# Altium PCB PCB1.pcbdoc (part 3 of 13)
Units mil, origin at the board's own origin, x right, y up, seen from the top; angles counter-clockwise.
Board outline 5895.51 x 5895.51 mil, 8 copper layers (Top Layer, L2_GND1, L3_SIG1, L4_GND2, L5_PWR, L6_SIG2, L7_GND3, Bottom Layer), stack 63.761 mil thick; 673 components, 558 nets, 2797 pads, 1861 vias.
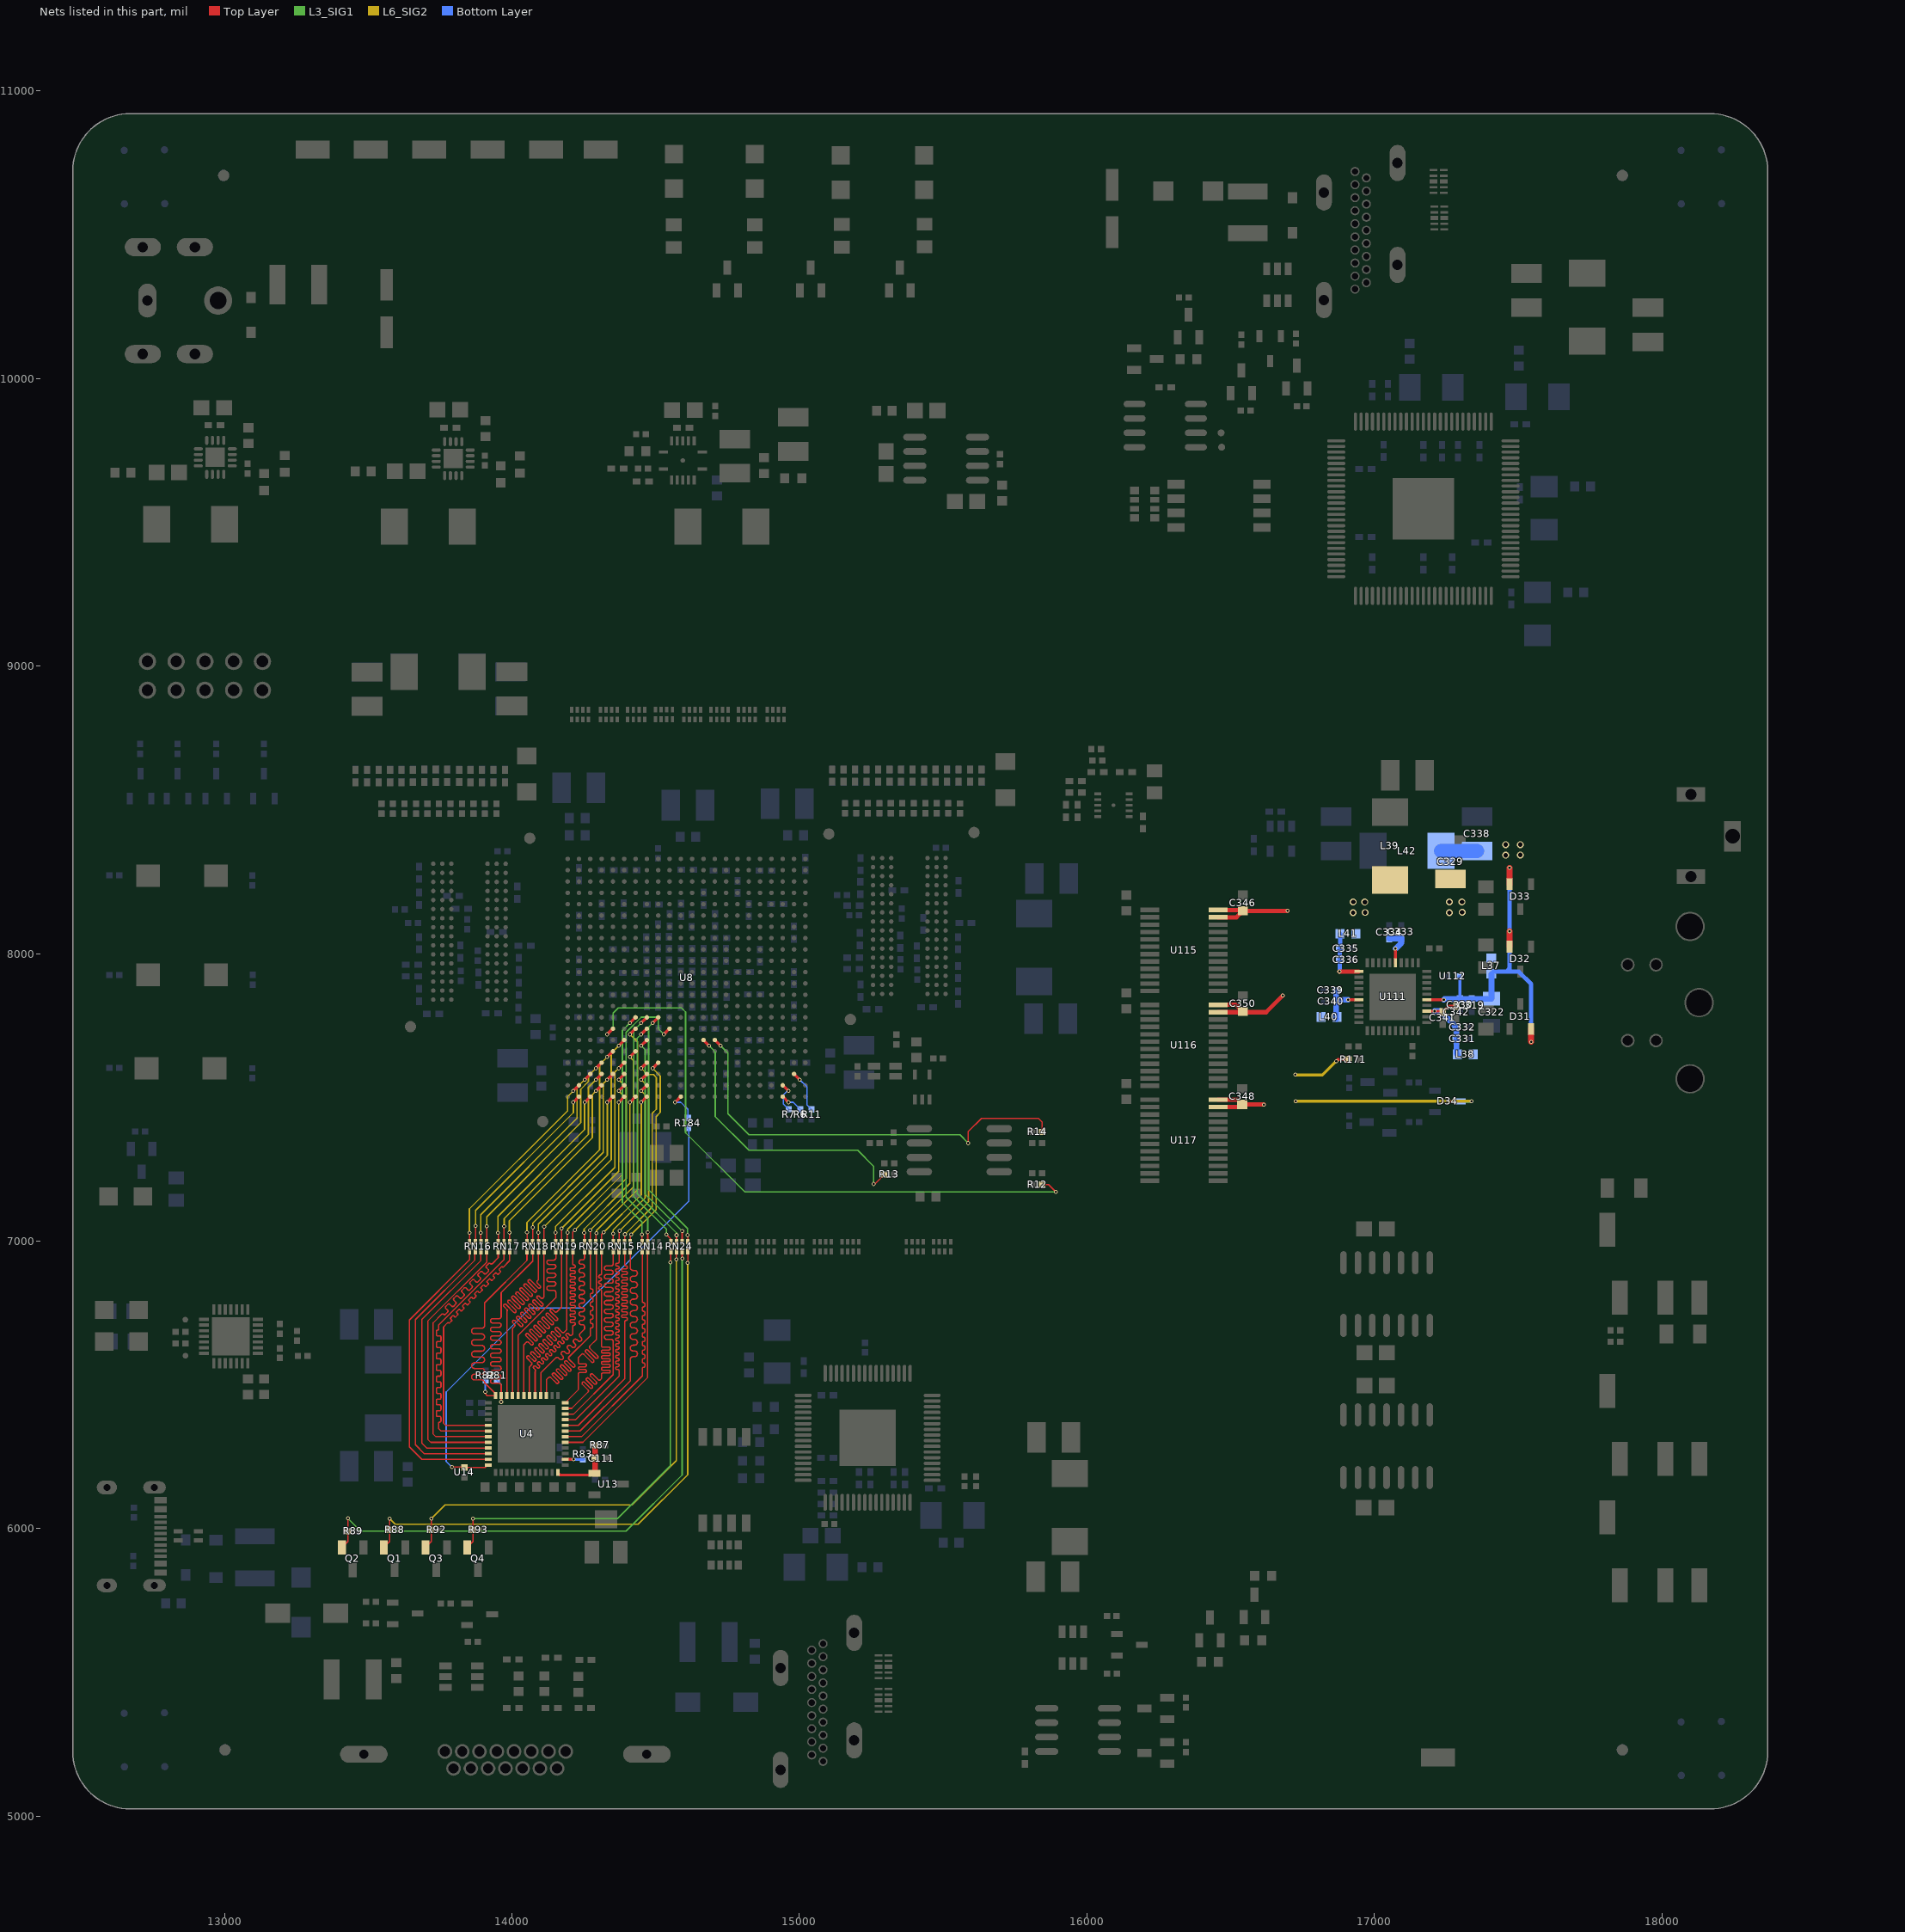
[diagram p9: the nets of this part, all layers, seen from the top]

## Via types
v1: diameter 23.62, hole 15.75, Top Layer to Bottom Layer, 621 vias
v2: diameter 13.8, hole 7.9, Top Layer to Bottom Layer, 567 vias
v3: diameter 13.78, hole 7.87, Top Layer to Bottom Layer, 529 vias
v4: diameter 13.78, hole 7.9, Top Layer to Bottom Layer, 114 vias
v5: diameter 15.75, hole 7.87, Top Layer to Bottom Layer, 16 vias
v6: diameter 24, hole 12, Top Layer to Bottom Layer, 10 vias
v7: diameter 11.81, hole 7.87, Top Layer to Bottom Layer, 4 vias

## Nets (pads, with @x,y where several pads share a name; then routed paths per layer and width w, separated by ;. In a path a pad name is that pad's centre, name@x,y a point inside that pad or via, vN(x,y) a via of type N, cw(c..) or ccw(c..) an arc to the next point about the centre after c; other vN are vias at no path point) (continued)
7125_B1: RN17.6 U4.17 | length 989.8
  Top Layer w4.7: U4.17@13917.5,6359.53 13769.83,6359.53 13762.36,6367 13762.36,6702 13776.14,6715.79 cw(c13777.91,6714.02) 13779.68,6715.79 ccw(c13781.45,6717.55) 13783.21,6715.79 13790.29,6722.86 ccw(c13788.52,6724.62) 13790.29,6726.39 13786.75,6729.93 cw(c13788.52,6731.7) 13786.75,6733.46 13793.82,6740.53 cw(c13795.59,6738.77) 13797.36,6740.53 13800.89,6737 ccw(c13802.66,6738.77) 13804.43,6737 13811.5,6744.07 ccw(c13809.73,6745.84) 13811.5,6747.61 13807.96,6751.14 cw(c13809.73,6752.91) 13807.96,6754.68 13815.03,6761.75 cw(c13816.8,6759.98) 13818.57,6761.75 13822.11,6758.21 ccw(c13823.87,6759.98) 13825.64,6758.21 13832.71,6765.28 ccw(c13830.94,6767.05) 13832.71,6768.82 13829.18,6772.35 cw(c13830.94,6774.12) 13829.18,6775.89 13836.25,6782.96 cw(c13838.02,6781.19) 13839.78,6782.96 13843.32,6779.43 ccw(c13845.09,6781.19) 13846.85,6779.43 13853.93,6786.5 ccw(c13852.16,6788.26) 13853.93,6790.03 13850.39,6793.57 cw(c13852.16,6795.34) 13850.39,6797.1 13857.46,6804.17 cw(c13859.23,6802.41) 13861,6804.17 13864.53,6800.64 ccw(c13866.3,6802.41) 13868.07,6800.64 13875.14,6807.71 ccw(c13873.37,6809.48) 13875.14,6811.25 13871.6,6814.78 cw(c13873.37,6816.55) 13871.6,6818.32 13878.67,6825.39 cw(c13880.44,6823.62) 13882.21,6825.39 13885.75,6821.85 ccw(c13887.51,6823.62) 13889.28,6821.85 13896.35,6828.92 ccw(c13894.58,6830.69) 13896.35,6832.46 13892.82,6835.99 cw(c13894.58,6837.76) 13892.82,6839.53 13899.89,6846.6 cw(c13901.66,6844.83) 13903.42,6846.6 13906.96,6843.07 ccw(c13908.73,6844.83) 13910.49,6843.07 13917.57,6850.14 ccw(c13915.8,6851.9) 13917.57,6853.67 13914.03,6857.21 cw(c13915.8,6858.98) 13914.03,6860.74 13921.1,6867.81 cw(c13922.87,6866.05) 13924.64,6867.81 13928.17,6864.28 ccw(c13929.94,6866.05) 13931.71,6864.28 13938.78,6871.35 ccw(c13937.01,6873.12) 13938.78,6874.89 13935.24,6878.42 cw(c13937.01,6880.19) 13935.24,6881.96 13942.31,6889.03 cw(c13944.08,6887.26) 13945.85,6889.03 13949.38,6885.49 ccw(c13951.15,6887.26) 13952.92,6885.49 13959.99,6892.56 ccw(c13958.22,6894.33) 13959.99,6896.1 13956.46,6899.63 cw(c13958.22,6901.4) 13956.46,6903.17 13963.53,6910.24 cw(c13965.29,6908.47) 13967.06,6910.24 ccw(c13968.83,6912.01) 13970.6,6910.24 13992.2,6931.84 RN17.6@13992.2,6964.17
7125_B1_FPGA: RN17.3 U8.AA4 | length 677.4
  Top Layer w4.7: v3(13991.36,7030) 13992.2,7029.16 RN17.3@13992.2,6997.83
  Top Layer w10: v2(14292.41,7522.32) U8.AA4@14312.08,7542
  L6_SIG2 w5: v3(13991.36,7030) 13991.36,7071 14279.56,7359.2 14279.56,7509.47 v2(14292.41,7522.32)
7125_B2: RN17.7 U4.18 | length 1083.4
  Top Layer w4.7: U4.18@13917.5,6339.84 13753.52,6339.84 13745.36,6348 13745.36,6366.62 cw(c13749.36,6366.62) 13749.36,6370.62 ccw(c13749.36,6374.62) 13753.36,6374.62 13753.36,6386.62 ccw(c13749.36,6386.62) 13749.36,6390.62 13741.36,6390.62 cw(c13741.36,6394.62) 13737.36,6394.62 13737.36,6406.62 cw(c13741.36,6406.62) 13741.36,6410.62 13749.36,6410.62 ccw(c13749.36,6414.62) 13753.36,6414.62 13753.36,6426.62 ccw(c13749.36,6426.62) 13749.36,6430.62 13741.36,6430.62 cw(c13741.36,6434.62) 13737.36,6434.62 13737.36,6446.62 cw(c13741.36,6446.62) 13741.36,6450.62 13749.36,6450.62 ccw(c13749.36,6454.62) 13753.36,6454.62 13753.36,6466.62 ccw(c13749.36,6466.62) 13749.36,6470.62 13741.36,6470.62 cw(c13741.36,6474.62) 13737.36,6474.62 13737.36,6486.62 cw(c13741.36,6486.62) 13741.36,6490.62 13749.36,6490.62 ccw(c13749.36,6494.62) 13753.36,6494.62 13753.36,6506.62 ccw(c13749.36,6506.62) 13749.36,6510.62 13741.36,6510.62 cw(c13741.36,6514.62) 13737.36,6514.62 13737.36,6526.62 cw(c13741.36,6526.62) 13741.36,6530.62 13749.36,6530.62 ccw(c13749.36,6534.62) 13753.36,6534.62 13753.36,6546.62 ccw(c13749.36,6546.62) 13749.36,6550.62 13741.36,6550.62 cw(c13741.36,6554.62) 13737.36,6554.62 13737.36,6566.62 cw(c13741.36,6566.62) 13741.36,6570.62 13749.36,6570.62 ccw(c13749.36,6574.62) 13753.36,6574.62 13753.36,6586.62 ccw(c13749.36,6586.62) 13749.36,6590.62 13741.36,6590.62 cw(c13741.36,6594.62) 13737.36,6594.62 13737.36,6606.62 cw(c13741.36,6606.62) 13741.36,6610.62 13749.36,6610.62 ccw(c13749.36,6614.62) 13753.36,6614.62 13753.36,6626.62 ccw(c13749.36,6626.62) 13749.36,6630.62 13741.36,6630.62 cw(c13741.36,6634.62) 13737.36,6634.62 13737.36,6646.62 cw(c13741.36,6646.62) 13741.36,6650.62 13749.36,6650.62 ccw(c13749.36,6654.62) 13753.36,6654.62 13753.36,6666.62 ccw(c13749.36,6666.62) 13749.36,6670.62 13741.36,6670.62 cw(c13741.36,6674.62) 13737.36,6674.62 13737.36,6686.62 cw(c13741.36,6686.62) 13741.36,6690.62 ccw(c13741.36,6694.62) 13745.36,6694.62 13745.36,6708.88 13972.52,6936.04 RN17.7@13972.52,6964.17
7125_B2_FPGA: RN17.2 U8.Y4 | length 724.4
  Top Layer w4.7: RN17.2@13972.52,6997.83 13972.52,7051.16 v3(13973.36,7052)
  Top Layer w10: v2(14292.41,7561.68) U8.Y4@14312.08,7581.35
  L6_SIG2 w5: v3(13973.36,7052) 13973.36,7079 14266.36,7372 14266.36,7536 14266.73,7536 v2(14292.41,7561.68)
7125_B3: RN17.8 U4.19 | length 1094.6
  Top Layer w4.7: U4.19@13917.5,6320.16 13735.2,6320.16 13726.36,6329 13726.36,6716.22 13755.78,6745.64 cw(c13759.06,6742.37) 13762.34,6745.64 ccw(c13765.61,6748.92) 13768.89,6745.64 13776.48,6753.23 ccw(c13773.2,6756.51) 13776.48,6759.79 13769.92,6766.34 cw(c13773.2,6769.62) 13769.92,6772.9 13777.51,6780.49 cw(c13780.78,6777.21) 13784.06,6780.49 13790.62,6773.93 ccw(c13793.9,6777.21) 13797.18,6773.93 13804.76,6781.51 ccw(c13801.48,6784.79) 13804.76,6788.07 13798.2,6794.63 cw(c13801.48,6797.91) 13798.2,6801.19 13805.79,6808.77 cw(c13809.07,6805.49) 13812.35,6808.77 13818.9,6802.21 ccw(c13822.18,6805.49) 13825.46,6802.21 13833.05,6809.8 ccw(c13829.77,6813.08) 13833.05,6816.35 13826.49,6822.91 cw(c13829.77,6826.19) 13826.49,6829.47 13834.07,6837.05 cw(c13837.35,6833.78) 13840.63,6837.05 13847.19,6830.5 ccw(c13850.47,6833.78) 13853.75,6830.5 13861.33,6838.08 ccw(c13858.05,6841.36) 13861.33,6844.64 13854.77,6851.2 cw(c13858.05,6854.47) 13854.77,6857.75 13862.36,6865.34 cw(c13865.64,6862.06) 13868.92,6865.34 13875.47,6858.78 ccw(c13878.75,6862.06) 13882.03,6858.78 13889.61,6866.37 ccw(c13886.34,6869.64) 13889.62,6872.92 13883.06,6879.48 cw(c13886.34,6882.76) 13883.06,6886.04 13890.64,6893.62 cw(c13893.92,6890.34) 13897.2,6893.62 13903.76,6887.07 ccw(c13907.04,6890.34) 13910.31,6887.07 13917.9,6894.65 ccw(c13914.62,6897.93) 13917.9,6901.21 13911.34,6907.76 cw(c13914.62,6911.04) 13911.34,6914.32 13918.93,6921.91 cw(c13922.21,6918.63) 13925.48,6921.91 ccw(c13928.76,6925.19) 13932.04,6921.91 13952.36,6942.22 13952.36,6963.7 RN17.8@13952.83,6964.17
7125_B3_FPGA: RN17.1 U8.AB3 | length 638.5
  Top Layer w4.7: v3(13951.36,7029) 13952.83,7027.53 RN17.1@13952.83,6997.83
  Top Layer w10: v2(14253.04,7482.92) U8.AB3@14272.71,7502.6
  L6_SIG2 w5: v3(13951.36,7029) 13951.36,7086 14253.04,7387.68 v2(14253.04,7482.92)
7125_B4: RN16.5 U4.20 | length 952.8
  Top Layer w4.7: RN16.5@13911.89,6964.17 13912.36,6963.7 13912.36,6927 13707.36,6722 13707.36,6311 13717.89,6300.47 U4.20@13917.5,6300.47
7125_B4_FPGA: RN16.4 U8.W4 | length 788.7
  Top Layer w4.7: RN16.4@13911.89,6997.83 13912.36,6998.3 v3(13912.36,7052)
  Top Layer w10: v2(14292.41,7601.05) U8.W4@14312.08,7620.73
  L6_SIG2 w5: v3(13912.36,7052) 13912.36,7085 14239.36,7412 14239.36,7528 14266.36,7555 14266.36,7575 v2(14292.41,7601.05)
7125_B5: RN16.6 U4.21 | length 989.8
  Top Layer w4.7: RN16.6@13892.2,6964.17 13892.36,6964.01 13892.36,6933 13686.36,6727 13686.36,6298 13703.57,6280.79 U4.21@13917.5,6280.79
7125_B5_FPGA: RN16.3 U8.Y3 | length 741.8
  Top Layer w4.7: v3(13891.36,7029) 13892.2,7028.16 RN16.3@13892.2,6997.83
  Top Layer w10: v2(14253.04,7561.68) U8.Y3@14272.71,7581.35
  L6_SIG2 w5: v3(13891.36,7029) 13891.36,7092 14226.73,7427.37 14226.73,7535.37 v2(14253.04,7561.68)
7125_B6: RN16.7 U4.22 | length 1024.3
  Top Layer w4.7: RN16.7@13872.52,6964.17 13871.36,6963.01 13871.36,6934 13664.36,6727 13664.36,6292 13695.26,6261.1 U4.22@13917.5,6261.1
7125_B6_FPGA: RN16.2 U8.AB2 | length 654.2
  Top Layer w4.7: RN16.2@13872.52,6997.83 13873.36,6998.67 v3(13873.36,7053)
  Top Layer w10: v2(14213.67,7482.92) U8.AB2@14233.34,7502.6
  L6_SIG2 w5: v3(13873.36,7053) 13873.36,7107 14213.67,7447.31 v2(14213.67,7482.92)
7125_B7: RN16.8 U4.23 | length 1058.1
  Top Layer w4.7: RN16.8@13852.83,6964.17 13852.36,6963.7 13852.36,6935 13643.36,6726 13643.36,6285 13686.94,6241.42 U4.23@13917.5,6241.42
7125_B7_FPGA: RN16.1 U8.AA2 | length 702.7
  Top Layer w4.7: v3(13852.36,7029) 13852.83,7028.53 RN16.1@13852.83,6997.83
  Top Layer w10: v2(14213.67,7522.32) U8.AA2@14233.34,7542
  L6_SIG2 w5: v3(13852.36,7029) 13852.36,7112 14193.36,7453 14193.36,7503 14194.35,7503 v2(14213.67,7522.32)
7125_BLK: R81.2 RN18.7 U4.11 | length 1143
  Top Layer w4.7: v3(13962.78,6441) U4.11@13962.78,6463.86 13962.78,6498 ccw(c13955.28,6498) 13955.28,6505.5 13933,6505.5 cw(c13933,6513) 13933,6520.5 13955.28,6520.5 ccw(c13955.28,6528) 13955.28,6535.5 13933,6535.5 cw(c13933,6543) 13933,6550.5 13955.28,6550.5 ccw(c13955.28,6558) 13955.28,6565.5 13933,6565.5 cw(c13933,6573) 13933,6580.5 13955.28,6580.5 ccw(c13955.28,6588) 13955.28,6595.5 13933,6595.5 cw(c13933,6603) 13933,6610.5 13955.28,6610.5 ccw(c13955.28,6618) 13955.28,6625.5 13933,6625.5 cw(c13933,6633) 13933,6640.5 13955.28,6640.5 ccw(c13955.28,6648) 13955.28,6655.5 13933,6655.5 cw(c13933,6663) 13933,6670.5 13955.28,6670.5 ccw(c13955.28,6678) 13955.28,6685.5 13933,6685.5 cw(c13933,6693) 13933,6700.5 13955.28,6700.5 ccw(c13955.28,6708) 13955.28,6715.5 13933,6715.5 cw(c13933,6723) 13933,6730.5 13955.28,6730.5 ccw(c13955.28,6738) 13962.78,6738 13962.78,6821.05 14072.52,6930.79 RN18.7@14072.52,6964.17
  Bottom Layer w4.7: R81.2@13948.36,6515.96 13962.78,6501.54 v3(13962.78,6441)
7125_BLK_FPGA: RN18.2 U8.Y5 | length 699.2
  Top Layer w4.7: v3(14072.36,7048) 14072.52,7047.84 RN18.2@14072.52,6997.83
  Top Layer w10: v2(14331.79,7561.68) U8.Y5@14351.46,7581.35
  L6_SIG2 w5: v3(14072.36,7048) 14072.36,7063 14318.18,7308.82 14318.18,7548.07 v2(14331.79,7561.68)
7125_CLK: R184.1 U4.24 U14.2 | length 1774.3
  Top Layer w4.7: v3(13791.3,6213.92) 13832.94,6213.92 U14.2@13834.24,6212.63 ; U14.2@13833.8,6212.32 13906.43,6212.32 U4.24@13915.64,6221.52
  Bottom Layer w4.7: v3(13791.3,6213.92) 13771.36,6233.87 13771.36,6475.24 14063.12,6767 14243.15,6767 14615.74,7139.58 14615.74,7388.51 14611.04,7393.21 R184.1@14611.04,7393.72
7125_CLK_FPGA: R184.2 U8.AB11 | length 112.5
  Top Layer w10: v2(14567.99,7482.92) U8.AB11@14587.66,7502.6
  Bottom Layer w4.7: v2(14567.99,7482.92) 14587.44,7482.92 14612.36,7458 R184.2@14612.36,7428.04
7125_G0: RN20.7 U4.3 | length 953.4
  Top Layer w4.7: U4.3@14120.26,6463.86 14120.26,6518.49 14127.87,6526.11 cw(c14131.4,6522.57) 14134.94,6526.11 14154.51,6506.53 ccw(c14158.05,6510.07) 14161.58,6513.6 14142.01,6533.18 cw(c14145.55,6536.71) 14149.08,6540.25 14168.66,6520.67 ccw(c14172.19,6524.21) 14175.73,6527.75 14156.15,6547.32 cw(c14159.69,6550.85) 14163.22,6554.39 14182.8,6534.82 ccw(c14186.33,6538.35) 14189.87,6541.89 14170.3,6561.46 cw(c14173.83,6565) 14177.37,6568.53 14196.94,6548.96 ccw(c14200.48,6552.49) 14204.01,6556.03 14184.44,6575.6 cw(c14187.97,6579.14) 14191.51,6582.67 14211.08,6563.1 ccw(c14214.62,6566.64) 14218.15,6570.17 14198.58,6589.75 cw(c14202.12,6593.28) 14198.58,6596.82 14272.52,6670.75 14272.52,6693.58 cw(c14277.44,6693.58) 14277.44,6698.5 ccw(c14277.44,6703.42) 14282.36,6703.42 14282.36,6708.58 ccw(c14277.44,6708.58) 14277.44,6713.5 cw(c14277.44,6718.42) 14272.52,6718.42 14272.52,6723.58 cw(c14277.44,6723.58) 14277.44,6728.5 ccw(c14277.44,6733.42) 14282.36,6733.42 14282.36,6738.58 ccw(c14277.44,6738.58) 14277.44,6743.5 cw(c14277.44,6748.42) 14272.52,6748.42 14272.52,6753.58 cw(c14277.44,6753.58) 14277.44,6758.5 ccw(c14277.44,6763.42) 14282.36,6763.42 14282.36,6768.58 ccw(c14277.44,6768.58) 14277.44,6773.5 cw(c14277.44,6778.42) 14272.52,6778.42 14272.52,6783.58 cw(c14277.44,6783.58) 14277.44,6788.5 ccw(c14277.44,6793.42) 14282.36,6793.42 14282.36,6798.58 ccw(c14277.44,6798.58) 14277.44,6803.5 cw(c14277.44,6808.42) 14272.52,6808.42 14272.52,6813.58 cw(c14277.44,6813.58) 14277.44,6818.5 ccw(c14277.44,6823.42) 14282.36,6823.42 14282.36,6828.58 ccw(c14277.44,6828.58) 14277.44,6833.5 cw(c14277.44,6838.42) 14272.52,6838.42 RN20.7@14272.52,6964.17
7125_G0_FPGA: RN20.2 U8.V7 | length 738.4
  Top Layer w4.7: v3(14272.36,7038) 14272.52,7037.84 RN20.2@14272.52,6997.83
  Top Layer w10: v2(14410.52,7640.42) U8.V7@14430.19,7660.1
  L6_SIG2 w5: v3(14272.36,7038) 14423.46,7189.1 14423.46,7627.48 v2(14410.52,7640.42)
7125_G1: RN20.8 U4.4 | length 881.3
  Top Layer w4.7: U4.4@14100.57,6463.86 14100.57,6541.83 14152.25,6593.52 cw(c14157.56,6588.22) 14162.86,6593.52 14166.48,6589.9 ccw(c14171.78,6595.2) 14177.08,6600.51 14173.47,6604.13 cw(c14178.77,6609.43) 14184.07,6614.73 14187.69,6611.11 ccw(c14192.99,6616.42) 14198.3,6621.72 14194.68,6625.34 cw(c14199.98,6630.64) 14205.29,6635.95 14208.9,6632.33 ccw(c14214.21,6637.63) 14219.51,6642.93 14215.89,6646.55 cw(c14221.2,6651.85) 14226.5,6657.16 14230.12,6653.54 ccw(c14235.42,6658.84) 14240.72,6664.15 14237.11,6667.76 cw(c14242.41,6673.07) 14237.11,6678.37 14252.83,6694.09 14252.83,6702.22 ccw(c14245.33,6702.22) 14245.33,6709.72 14240.86,6709.72 cw(c14240.86,6717.22) 14240.86,6724.72 14245.33,6724.72 ccw(c14245.33,6732.22) 14245.33,6739.72 14240.86,6739.72 cw(c14240.86,6747.22) 14240.86,6754.72 14245.33,6754.72 ccw(c14245.33,6762.22) 14245.33,6769.72 14240.86,6769.72 cw(c14240.86,6777.22) 14240.86,6784.72 14245.33,6784.72 ccw(c14245.33,6792.22) 14245.33,6799.72 14240.86,6799.72 cw(c14240.86,6807.22) 14240.86,6814.72 14245.33,6814.72 ccw(c14245.33,6822.22) 14245.33,6829.72 14240.86,6829.72 cw(c14240.86,6837.22) 14240.86,6844.72 14245.33,6844.72 ccw(c14245.33,6852.22) 14245.33,6859.72 14240.86,6859.72 cw(c14240.86,6867.22) 14240.86,6874.72 14245.33,6874.72 ccw(c14245.33,6882.22) 14245.33,6889.72 14240.86,6889.72 cw(c14240.86,6897.22) 14240.86,6904.72 14245.33,6904.72 ccw(c14245.33,6912.22) 14245.33,6919.72 14240.86,6919.72 cw(c14240.86,6927.22) 14240.86,6934.72 14245.33,6934.72 ccw(c14245.33,6942.22) 14252.83,6942.22 RN20.8@14252.83,6964.17
7125_G1_FPGA: RN20.1 U8.AB7 | length 579.5
  Top Layer w4.7: v3(14251.36,7029) 14252.83,7027.53 RN20.1@14252.83,6997.83
  Top Layer w10: v2(14410.52,7482.92) U8.AB7@14430.19,7502.6
  L6_SIG2 w5: v3(14251.36,7029) 14251.36,7042 14410.52,7201.16 v2(14410.52,7482.92)
7125_G2: RN19.5 U4.5 | length 1065.4
  Top Layer w4.7: U4.5@14080.89,6463.86 14080.89,6546.05 ccw(c14077.35,6549.58) 14080.89,6553.12 14076.31,6557.7 cw(c14079.84,6561.23) 14083.38,6564.77 14087.96,6560.19 ccw(c14091.49,6563.72) 14095.03,6567.26 14090.45,6571.84 cw(c14093.99,6575.37) 14097.52,6578.91 14102.1,6574.33 ccw(c14105.64,6577.87) 14109.17,6581.4 14104.59,6585.98 cw(c14108.13,6589.52) 14111.66,6593.05 14116.24,6588.47 ccw(c14119.78,6592.01) 14123.31,6595.54 14118.73,6600.12 cw(c14122.27,6603.66) 14125.81,6607.19 14130.38,6602.61 ccw(c14133.92,6606.15) 14137.46,6609.69 14132.88,6614.27 cw(c14136.41,6617.8) 14139.95,6621.34 14144.53,6616.76 ccw(c14148.06,6620.29) 14151.6,6623.83 14147.02,6628.41 cw(c14150.55,6631.94) 14154.09,6635.48 14158.67,6630.9 ccw(c14162.2,6634.43) 14165.74,6637.97 14161.16,6642.55 cw(c14164.7,6646.09) 14168.23,6649.62 14172.81,6645.04 ccw(c14176.35,6648.58) 14179.88,6652.11 14175.3,6656.69 cw(c14178.84,6660.23) 14182.37,6663.76 14186.95,6659.18 ccw(c14190.49,6662.72) 14194.02,6666.25 14189.44,6670.83 cw(c14192.98,6674.37) 14196.52,6677.9 14201.1,6673.32 ccw(c14204.63,6676.86) 14208.17,6673.32 14211.36,6676.52 14211.36,6702.67 cw(c14215.83,6702.67) 14215.83,6707.15 ccw(c14215.83,6711.63) 14220.31,6711.63 14220.31,6712.67 ccw(c14215.83,6712.67) 14215.83,6717.15 14206.88,6717.15 cw(c14206.88,6721.63) 14202.4,6721.63 14202.4,6722.67 cw(c14206.88,6722.67) 14206.88,6727.15 14215.83,6727.15 ccw(c14215.83,6731.63) 14220.31,6731.63 14220.31,6732.67 ccw(c14215.83,6732.67) 14215.83,6737.15 14206.88,6737.15 cw(c14206.88,6741.63) 14202.4,6741.63 14202.4,6742.67 cw(c14206.88,6742.67) 14206.88,6747.15 14215.83,6747.15 ccw(c14215.83,6751.63) 14220.31,6751.63 14220.31,6752.67 ccw(c14215.83,6752.67) 14215.83,6757.15 14206.88,6757.15 cw(c14206.88,6761.63) 14202.4,6761.63 14202.4,6762.67 cw(c14206.88,6762.67) 14206.88,6767.15 14215.83,6767.15 ccw(c14215.83,6771.63) 14220.31,6771.63 14220.31,6772.67 ccw(c14215.83,6772.67) 14215.83,6777.15 14206.88,6777.15 cw(c14206.88,6781.63) 14202.4,6781.63 14202.4,6782.67 cw(c14206.88,6782.67) 14206.88,6787.15 14215.83,6787.15 ccw(c14215.83,6791.63) 14220.31,6791.63 14220.31,6792.67 ccw(c14215.83,6792.67) 14215.83,6797.15 14206.88,6797.15 cw(c14206.88,6801.63) 14202.4,6801.63 14202.4,6802.67 cw(c14206.88,6802.67) 14206.88,6807.15 14215.83,6807.15 ccw(c14215.83,6811.63) 14220.31,6811.63 14220.31,6812.67 ccw(c14215.83,6812.67) 14215.83,6817.15 14206.88,6817.15 cw(c14206.88,6821.63) 14202.4,6821.63 14202.4,6822.67 cw(c14206.88,6822.67) 14206.88,6827.15 14215.83,6827.15 ccw(c14215.83,6831.63) 14220.31,6831.63 14220.31,6832.67 ccw(c14215.83,6832.67) 14215.83,6837.15 14206.88,6837.15 cw(c14206.88,6841.63) 14202.4,6841.63 14202.4,6842.67 cw(c14206.88,6842.67) 14206.88,6847.15 14215.83,6847.15 ccw(c14215.83,6851.63) 14220.31,6851.63 14220.31,6852.67 ccw(c14215.83,6852.67) 14215.83,6857.15 14206.88,6857.15 cw(c14206.88,6861.63) 14202.4,6861.63 14202.4,6862.67 cw(c14206.88,6862.67) 14206.88,6867.15 14215.83,6867.15 ccw(c14215.83,6871.63) 14220.31,6871.63 14220.31,6872.67 ccw(c14215.83,6872.67) 14215.83,6877.15 14206.88,6877.15 cw(c14206.88,6881.63) 14202.4,6881.63 14202.4,6882.67 cw(c14206.88,6882.67) 14206.88,6887.15 14215.83,6887.15 ccw(c14215.83,6891.63) 14220.31,6891.63 14220.31,6892.67 ccw(c14215.83,6892.67) 14215.83,6897.15 14206.88,6897.15 cw(c14206.88,6901.63) 14202.4,6901.63 14202.4,6902.67 cw(c14206.88,6902.67) 14206.88,6907.15 14215.83,6907.15 ccw(c14215.83,6911.63) 14220.31,6911.63 14220.31,6912.67 ccw(c14215.83,6912.67) 14215.83,6917.15 cw(c14215.83,6921.63) 14211.36,6921.63 14211.36,6963.64 RN19.5@14211.89,6964.17
7125_G2_FPGA: RN19.4 U8.Y6 | length 679.6
  Top Layer w4.7: RN19.4@14211.89,6997.83 14211.89,7031.53 v3(14219.36,7039)
  Top Layer w10: v2(14371.15,7561.68) U8.Y6@14390.82,7581.35
  L6_SIG2 w5: v3(14219.36,7039) 14397.67,7217.31 14397.67,7535.16 v2(14371.15,7561.68)
7125_G3: RN19.6 U4.6 | length 998.8
  Top Layer w4.7: U4.6@14061.2,6463.86 14061.2,6562.65 14068.53,6569.98 ccw(c14065,6573.52) 14068.53,6577.05 14052.94,6592.65 cw(c14056.47,6596.18) 14060.01,6599.72 14075.6,6584.12 ccw(c14079.14,6587.66) 14082.67,6591.19 14067.08,6606.79 cw(c14070.61,6610.32) 14074.15,6613.86 14089.74,6598.26 ccw(c14093.28,6601.8) 14096.82,6605.34 14081.22,6620.93 cw(c14084.76,6624.47) 14088.29,6628 14103.89,6612.41 ccw(c14107.42,6615.94) 14110.96,6619.48 14095.36,6635.07 cw(c14098.9,6638.61) 14102.43,6642.14 14118.03,6626.55 ccw(c14121.56,6630.08) 14125.1,6633.62 14109.5,6649.22 cw(c14113.04,6652.75) 14116.58,6656.29 14132.17,6640.69 ccw(c14135.71,6644.23) 14139.24,6647.76 14123.65,6663.36 cw(c14127.18,6666.89) 14130.72,6670.43 14146.31,6654.83 ccw(c14149.85,6658.37) 14153.38,6661.9 14137.79,6677.5 cw(c14141.32,6681.03) 14144.86,6684.57 14160.46,6668.98 ccw(c14163.99,6672.51) 14167.53,6676.05 14151.93,6691.64 cw(c14155.47,6695.18) 14159,6698.71 14174.6,6683.12 ccw(c14178.13,6686.65) 14181.67,6683.12 14191.36,6692.81 14191.36,6963.33 RN19.6@14192.2,6964.17
7125_G3_FPGA: RN19.3 U8.AA6 | length 637.4
  Top Layer w4.7: RN19.3@14192.2,6997.83 14192.2,7028.84 v3(14193.36,7030)
  Top Layer w10: v2(14371.15,7522.32) U8.AA6@14390.82,7542
  L6_SIG2 w5: v3(14193.36,7030) 14193.36,7041 14384.36,7232 14384.36,7509.11 v2(14371.15,7522.32)
7125_G4: RN19.7 U4.7 | length 1092.3
  Top Layer w4.7: U4.7@14041.52,6463.86 14041.52,6639.39 14050.53,6648.4 cw(c14054.06,6644.86) 14057.6,6648.4 14065.73,6640.26 ccw(c14069.27,6643.8) 14072.8,6647.33 14049.46,6670.68 cw(c14053,6674.21) 14056.53,6677.75 14079.87,6654.41 ccw(c14083.41,6657.94) 14086.95,6661.48 14063.6,6684.82 cw(c14067.14,6688.35) 14070.67,6691.89 14094.02,6668.55 ccw(c14097.55,6672.08) 14101.09,6675.62 14077.75,6698.96 cw(c14081.28,6702.5) 14084.82,6706.03 14108.16,6682.69 ccw(c14111.69,6686.23) 14115.23,6689.76 14091.89,6713.1 cw(c14095.42,6716.64) 14098.96,6720.17 14122.3,6696.83 ccw(c14125.84,6700.37) 14129.37,6703.9 14106.03,6727.24 cw(c14109.57,6730.78) 14113.1,6734.32 14136.44,6710.97 ccw(c14139.98,6714.51) 14143.51,6718.05 14120.17,6741.39 cw(c14123.71,6744.92) 14127.24,6748.46 14150.58,6725.12 ccw(c14154.12,6728.65) 14157.66,6732.19 14134.31,6755.53 cw(c14137.85,6759.06) 14141.39,6762.6 14149.52,6754.46 ccw(c14153.06,6758) 14156.59,6754.46 14172.52,6770.39 RN19.7@14172.52,6964.17
7125_G4_FPGA: RN19.2 U8.AB6 | length 595.3
  Top Layer w4.7: v3(14172.36,7044) 14172.52,7043.84 RN19.2@14172.52,6997.83
  Top Layer w10: v2(14371.15,7482.92) U8.AB6@14390.82,7502.6
  L6_SIG2 w5: v3(14172.36,7044) 14371.15,7242.79 v2(14371.15,7482.92)
7125_G5: RN19.8 U4.8 | length 754.1
  Top Layer w4.7: U4.8@14021.83,6463.86 14021.83,6672.47 14152.83,6803.47 14152.83,6821.67 ccw(c14145.33,6821.67) 14145.33,6829.17 14128.95,6829.17 cw(c14128.95,6836.67) 14128.95,6844.17 14145.33,6844.17 ccw(c14145.33,6851.67) 14145.33,6859.17 14128.95,6859.17 cw(c14128.95,6866.67) 14128.95,6874.17 14145.33,6874.17 ccw(c14145.33,6881.67) 14145.33,6889.17 14128.95,6889.17 cw(c14128.95,6896.67) 14128.95,6904.17 14145.33,6904.17 ccw(c14145.33,6911.67) 14145.33,6919.17 14128.95,6919.17 cw(c14128.95,6926.67) 14128.95,6934.17 14145.33,6934.17 ccw(c14145.33,6941.67) 14152.83,6941.67 RN19.8@14152.83,6964.17
7125_G5_FPGA: RN19.1 U8.W6 | length 721.9
  Top Layer w4.7: v3(14152.36,7030) 14152.36,6998.3 RN19.1@14152.83,6997.83
  Top Layer w10: v2(14371.15,7601.05) U8.W6@14390.82,7620.73
  L6_SIG2 w5: v3(14152.36,7030) 14152.36,7051 14358.1,7256.74 14358.1,7588 v2(14371.15,7601.05)
7125_G6: RN18.5 U4.9 | length 960
  Top Layer w4.7: U4.9@14002.15,6463.86 14002.15,6696.34 14009.26,6703.45 ccw(c14005.72,6706.98) 14009.26,6710.52 14003.43,6716.35 cw(c14006.96,6719.88) 14010.5,6723.42 14029.23,6704.69 ccw(c14032.76,6708.23) 14036.3,6711.76 14017.57,6730.49 cw(c14021.11,6734.02) 14024.64,6737.56 14043.37,6718.83 ccw(c14046.9,6722.37) 14050.44,6725.9 14031.71,6744.63 cw(c14035.25,6748.17) 14038.78,6751.7 14057.51,6732.98 ccw(c14061.05,6736.51) 14064.58,6740.05 14045.86,6758.77 cw(c14049.39,6762.31) 14052.93,6765.84 14071.65,6747.12 ccw(c14075.19,6750.65) 14078.72,6754.19 14060,6772.92 cw(c14063.53,6776.45) 14067.07,6779.99 14085.79,6761.26 ccw(c14089.33,6764.8) 14092.87,6768.33 14074.14,6787.06 cw(c14077.67,6790.59) 14081.21,6794.13 14099.94,6775.4 ccw(c14103.47,6778.94) 14107.01,6782.47 14088.28,6801.2 cw(c14091.82,6804.74) 14095.35,6808.27 14101.18,6802.44 ccw(c14104.72,6805.98) 14108.25,6802.44 14111.36,6805.55 14111.36,6963.64 RN18.5@14111.89,6964.17
7125_G6_FPGA: RN18.4 U8.U6 | length 817.2
  Top Layer w4.7: RN18.4@14111.89,6997.83 14111.89,7049.53 v3(14112.36,7050)
  Top Layer w10: v2(14371.15,7679.79) U8.U6@14390.82,7699.47
  L6_SIG2 w5: v3(14112.36,7050) 14345.36,7283 14345.36,7654 v2(14371.15,7679.79)
7125_G7: RN18.6 U4.10 | length 1149.5
  Top Layer w4.7: U4.10@13982.46,6463.86 13982.46,6755.6 ccw(c13978.92,6759.13) 13982.46,6762.67 13972.66,6772.47 cw(c13976.19,6776) 13979.73,6779.54 14006.4,6752.87 ccw(c14009.93,6756.41) 14013.47,6759.94 13986.8,6786.61 cw(c13990.34,6790.14) 13993.87,6793.68 14020.54,6767.01 ccw(c14024.08,6770.55) 14027.61,6774.08 14000.94,6800.75 cw(c14004.48,6804.29) 14008.01,6807.82 14034.68,6781.16 ccw(c14038.22,6784.69) 14041.75,6788.23 14015.09,6814.89 cw(c14018.62,6818.43) 14022.16,6821.96 14048.82,6795.3 ccw(c14052.36,6798.83) 14055.9,6802.37 14029.23,6829.04 cw(c14032.76,6832.57) 14036.3,6836.11 14062.97,6809.44 ccw(c14066.5,6812.98) 14070.04,6816.51 14043.37,6843.18 cw(c14046.91,6846.71) 14050.44,6850.25 14077.11,6823.58 ccw(c14080.64,6827.12) 14084.18,6830.65 14057.51,6857.32 cw(c14061.05,6860.86) 14064.58,6864.39 14091.25,6837.72 ccw(c14094.79,6841.26) 14098.32,6844.79 14088.52,6854.59 cw(c14092.06,6858.13) 14088.52,6861.66 14092.36,6865.5 14092.36,6964.01 RN18.6@14092.2,6964.17
7125_G7_FPGA: RN18.3 U8.AB5 | length 612.2
  Top Layer w4.7: RN18.3@14092.2,6997.83 14092.2,7029.84 v3(14092.36,7030)
  Top Layer w10: v2(14331.79,7482.92) U8.AB5@14351.46,7502.6
  L6_SIG2 w5: v3(14092.36,7030) 14092.36,7059 14331.79,7298.43 v2(14331.79,7482.92)
7125_PS: R83.1 U4.38 | length 64.2
  Top Layer w10: U4.38@14185.22,6241.42 v3(14214.36,6241.42)
  Bottom Layer w10: v3(14214.36,6241.42) 14248.59,6241.42 R83.1@14249.17,6240.84
7125_R0: RN14.7 U4.41 | length 818.8
  Top Layer w4.7: U4.41@14185.22,6300.47 14246.83,6300.47 14472.38,6526.02 14472.38,6964.03 RN14.7@14472.52,6964.17
7125_R0_FPGA: RN14.2 U8.T10 | length 985
  Top Layer w4.7: v3(14472.36,7031) 14472.52,7030.84 RN14.2@14472.52,6997.83
  Top Layer w10: v2(14528.63,7719.16) U8.T10@14548.3,7738.84
  L3_SIG1 w5: v3(14472.36,7031) 14472.36,7078.57 14397.36,7153.57 14397.36,7726 14450.36,7779 14499.36,7779 14500.36,7780 14509.36,7771 14509.36,7738.43 v2(14528.63,7719.16)
7125_R1: RN14.8 U4.42 | length 869.8
  Top Layer w4.7: U4.42@14185.22,6320.16 14242.52,6320.16 14453.51,6531.15 14453.51,6556.86 cw(c14457.93,6556.86) 14457.93,6561.28 ccw(c14457.93,6565.71) 14462.36,6565.71 14462.36,6571.86 ccw(c14457.93,6571.86) 14457.93,6576.28 cw(c14457.93,6580.71) 14453.51,6580.71 14453.51,6586.86 cw(c14457.93,6586.86) 14457.93,6591.28 ccw(c14457.93,6595.71) 14462.36,6595.71 14462.36,6601.86 ccw(c14457.93,6601.86) 14457.93,6606.28 cw(c14457.93,6610.71) 14453.51,6610.71 14453.51,6616.86 cw(c14457.93,6616.86) 14457.93,6621.28 ccw(c14457.93,6625.71) 14462.36,6625.71 14462.36,6631.86 ccw(c14457.93,6631.86) 14457.93,6636.28 cw(c14457.93,6640.71) 14453.51,6640.71 14453.51,6646.86 cw(c14457.93,6646.86) 14457.93,6651.28 ccw(c14457.93,6655.71) 14462.36,6655.71 14462.36,6661.86 ccw(c14457.93,6661.86) 14457.93,6666.28 cw(c14457.93,6670.71) 14453.51,6670.71 14453.51,6676.86 cw(c14457.93,6676.86) 14457.93,6681.28 ccw(c14457.93,6685.71) 14462.36,6685.71 14462.36,6691.86 ccw(c14457.93,6691.86) 14457.93,6696.28 cw(c14457.93,6700.71) 14453.51,6700.71 14453.51,6706.86 cw(c14457.93,6706.86) 14457.93,6711.28 ccw(c14457.93,6715.71) 14462.36,6715.71 14462.36,6721.86 ccw(c14457.93,6721.86) 14457.93,6726.28 cw(c14457.93,6730.71) 14453.51,6730.71 14453.51,6736.86 cw(c14457.93,6736.86) 14457.93,6741.28 ccw(c14457.93,6745.71) 14462.36,6745.71 14462.36,6751.86 ccw(c14457.93,6751.86) 14457.93,6756.28 cw(c14457.93,6760.71) 14453.51,6760.71 14453.51,6766.86 cw(c14457.93,6766.86) 14457.93,6771.28 ccw(c14457.93,6775.71) 14462.36,6775.71 14462.36,6781.86 ccw(c14457.93,6781.86) 14457.93,6786.28 cw(c14457.93,6790.71) 14453.51,6790.71 14453.51,6963.49 RN14.8@14452.83,6964.17
7125_R1_FPGA: RN14.1 U8.R7 | length 827.7
  Top Layer w4.7: v3(14452.36,7023) 14452.83,7022.53 RN14.1@14452.83,6997.83
  Top Layer w10: v2(14410.52,7758.52) U8.R7@14430.19,7778.2
  L3_SIG1 w5: v2(14410.52,7758.52) 14384.36,7732.36 14384.36,7134.69 14452.36,7066.69 v3(14452.36,7023)
7125_R2: RN15.5 U4.43 | length 1011.5
  Top Layer w4.7: U4.43@14185.22,6339.84 14237.2,6339.84 14411.68,6514.32 14411.68,6588.29 cw(c14421.68,6588.29) 14421.68,6598.29 14426.69,6598.29 ccw(c14426.69,6608.29) 14426.69,6618.29 14421.68,6618.29 cw(c14421.68,6628.29) 14421.68,6638.29 14426.69,6638.29 ccw(c14426.69,6648.29) 14426.69,6658.29 14421.68,6658.29 cw(c14421.68,6668.29) 14421.68,6678.29 14426.69,6678.29 ccw(c14426.69,6688.29) 14426.69,6698.29 14421.68,6698.29 cw(c14421.68,6708.29) 14421.68,6718.29 14426.69,6718.29 ccw(c14426.69,6728.29) 14426.69,6738.29 14421.68,6738.29 cw(c14421.68,6748.29) 14421.68,6758.29 14426.69,6758.29 ccw(c14426.69,6768.29) 14426.69,6778.29 14421.68,6778.29 cw(c14421.68,6788.29) 14421.68,6798.29 14426.69,6798.29 ccw(c14426.69,6808.29) 14426.69,6818.29 14421.68,6818.29 cw(c14421.68,6828.29) 14421.68,6838.29 14426.69,6838.29 ccw(c14426.69,6848.29) 14426.69,6858.29 14421.68,6858.29 cw(c14421.68,6868.29) 14421.68,6878.29 14426.69,6878.29 ccw(c14426.69,6888.29) 14426.69,6898.29 14421.68,6898.29 cw(c14421.68,6908.29) 14411.68,6908.29 14411.68,6963.96 RN15.5@14411.89,6964.17
7125_R2_FPGA: RN15.4 U8.W9 | length 685.1
  Top Layer w4.7: RN15.4@14411.89,6997.83 14411.89,7019.53 v3(14415.36,7023)
  Top Layer w10: v2(14489.26,7601.05) U8.W9@14508.93,7620.73
  L6_SIG2 w5: v3(14415.36,7023) 14501.36,7109 14501.36,7433 14515.78,7447.42 14515.78,7574.53 v2(14489.26,7601.05)
7125_R3: RN15.6 U4.44 | length 1016.2
  Top Layer w4.7: U4.44@14185.22,6359.53 14230.89,6359.53 14391.94,6520.58 14391.94,6719.21 cw(c14396.94,6719.21) 14396.94,6724.21 14397.07,6724.21 ccw(c14397.07,6729.21) 14397.07,6734.21 14386.81,6734.21 cw(c14386.81,6739.21) 14386.81,6744.21 14397.07,6744.21 ccw(c14397.07,6749.21) 14397.07,6754.21 14386.81,6754.21 cw(c14386.81,6759.21) 14386.81,6764.21 14397.07,6764.21 ccw(c14397.07,6769.21) 14397.07,6774.21 14386.81,6774.21 cw(c14386.81,6779.21) 14386.81,6784.21 14397.07,6784.21 ccw(c14397.07,6789.21) 14397.07,6794.21 14386.81,6794.21 cw(c14386.81,6799.21) 14386.81,6804.21 14397.07,6804.21 ccw(c14397.07,6809.21) 14397.07,6814.21 14386.81,6814.21 cw(c14386.81,6819.21) 14386.81,6824.21 14397.07,6824.21 ccw(c14397.07,6829.21) 14397.07,6834.21 14386.81,6834.21 cw(c14386.81,6839.21) 14386.81,6844.21 14397.07,6844.21 ccw(c14397.07,6849.21) 14397.07,6854.21 14386.81,6854.21 cw(c14386.81,6859.21) 14386.81,6864.21 14397.07,6864.21 ccw(c14397.07,6869.21) 14397.07,6874.21 14386.81,6874.21 cw(c14386.81,6879.21) 14386.81,6884.21 14397.07,6884.21 ccw(c14397.07,6889.21) 14397.07,6894.21 14386.81,6894.21 cw(c14386.81,6899.21) 14386.81,6904.21 14397.07,6904.21 ccw(c14397.07,6909.21) 14397.07,6914.21 14396.94,6914.21 cw(c14396.94,6919.21) 14391.94,6919.21 14391.94,6963.91 RN15.6@14392.2,6964.17
7125_R3_FPGA: RN15.3 U8.W8 | length 710.4
  Top Layer w4.7: RN15.3@14392.2,6997.83 14392.2,7022.84 v3(14393.36,7024)
  Top Layer w10: v2(14449.89,7601.05) U8.W8@14469.56,7620.73
  L6_SIG2 w5: v3(14393.36,7024) 14488.36,7119 14488.36,7445 14502.36,7459 14502.36,7569 14492.36,7579 14471.94,7579 v2(14449.89,7601.05)
7125_R4: RN15.7 U4.45 | length 982.8
  Top Layer w4.7: U4.45@14185.22,6379.21 14221.57,6379.21 14373.04,6530.68 14373.04,6548.42 ccw(c14368.04,6548.42) 14368.04,6553.42 14365.89,6553.42 cw(c14365.89,6558.42) 14365.89,6563.42 14368.04,6563.42 ccw(c14368.04,6568.42) 14368.04,6573.42 14365.89,6573.42 cw(c14365.89,6578.42) 14365.89,6583.42 14368.04,6583.42 ccw(c14368.04,6588.42) 14368.04,6593.42 14365.89,6593.42 cw(c14365.89,6598.42) 14365.89,6603.42 14368.04,6603.42 ccw(c14368.04,6608.42) 14368.04,6613.42 14365.89,6613.42 cw(c14365.89,6618.42) 14365.89,6623.42 14368.04,6623.42 ccw(c14368.04,6628.42) 14368.04,6633.42 14365.89,6633.42 cw(c14365.89,6638.42) 14365.89,6643.42 14368.04,6643.42 ccw(c14368.04,6648.42) 14368.04,6653.42 14365.89,6653.42 cw(c14365.89,6658.42) 14365.89,6663.42 14368.04,6663.42 ccw(c14368.04,6668.42) 14368.04,6673.42 14365.89,6673.42 cw(c14365.89,6678.42) 14365.89,6683.42 14368.04,6683.42 ccw(c14368.04,6688.42) 14368.04,6693.42 14365.89,6693.42 cw(c14365.89,6698.42) 14365.89,6703.42 14368.04,6703.42 ccw(c14368.04,6708.42) 14368.04,6713.42 14365.89,6713.42 cw(c14365.89,6718.42) 14365.89,6723.42 14368.04,6723.42 ccw(c14368.04,6728.42) 14368.04,6733.42 14365.89,6733.42 cw(c14365.89,6738.42) 14365.89,6743.42 14368.04,6743.42 ccw(c14368.04,6748.42) 14368.04,6753.42 14365.89,6753.42 cw(c14365.89,6758.42) 14365.89,6763.42 14368.04,6763.42 ccw(c14368.04,6768.42) 14368.04,6773.42 14365.89,6773.42 cw(c14365.89,6778.42) 14365.89,6783.42 14368.04,6783.42 ccw(c14368.04,6788.42) 14368.04,6793.42 14365.89,6793.42 cw(c14365.89,6798.42) 14365.89,6803.42 14368.04,6803.42 ccw(c14368.04,6808.42) 14368.04,6813.42 14365.89,6813.42 cw(c14365.89,6818.42) 14365.89,6823.42 14368.04,6823.42 ccw(c14368.04,6828.42) 14368.04,6833.42 14365.89,6833.42 cw(c14365.89,6838.42) 14365.89,6843.42 14368.04,6843.42 ccw(c14368.04,6848.42) 14368.04,6853.42 14365.89,6853.42 cw(c14365.89,6858.42) 14365.89,6863.42 14368.04,6863.42 ccw(c14368.04,6868.42) 14368.04,6873.42 14365.89,6873.42 cw(c14365.89,6878.42) 14365.89,6883.42 14368.04,6883.42 ccw(c14368.04,6888.42) 14368.04,6893.42 14365.89,6893.42 cw(c14365.89,6898.42) 14365.89,6903.42 14368.04,6903.42 ccw(c14368.04,6908.42) 14368.04,6913.42 14365.89,6913.42 cw(c14365.89,6918.42) 14365.89,6923.42 14368.04,6923.42 ccw(c14368.04,6928.42) 14373.04,6928.42 14373.04,6963.65 RN15.7@14372.52,6964.17
7125_R4_FPGA: RN15.2 U8.Y8 | length 644.8
  Top Layer w4.7: RN15.2@14372.52,6997.83 14372.52,7034.16 v3(14374.36,7036)
  Top Layer w10: v2(14449.89,7561.68) U8.Y8@14469.56,7581.35
  L6_SIG2 w5: v3(14374.36,7036) 14475.36,7137 14475.36,7536.21 v2(14449.89,7561.68)
7125_R5: RN15.8 U4.46 | length 1091.5
  Top Layer w4.7: U4.46@14185.22,6398.9 14215.26,6398.9 14352.36,6536 14352.36,6651.23 ccw(c14344.86,6651.23) 14344.86,6658.73 14329.02,6658.73 cw(c14329.02,6666.23) 14329.02,6673.73 14344.86,6673.73 ccw(c14344.86,6681.23) 14344.86,6688.73 14329.02,6688.73 cw(c14329.02,6696.23) 14329.02,6703.73 14344.86,6703.73 ccw(c14344.86,6711.23) 14344.86,6718.73 14329.02,6718.73 cw(c14329.02,6726.23) 14329.02,6733.73 14344.86,6733.73 ccw(c14344.86,6741.23) 14344.86,6748.73 14329.02,6748.73 cw(c14329.02,6756.23) 14329.02,6763.73 14344.86,6763.73 ccw(c14344.86,6771.23) 14344.86,6778.73 14329.02,6778.73 cw(c14329.02,6786.23) 14329.02,6793.73 14344.86,6793.73 ccw(c14344.86,6801.23) 14344.86,6808.73 14329.02,6808.73 cw(c14329.02,6816.23) 14329.02,6823.73 14344.86,6823.73 ccw(c14344.86,6831.23) 14344.86,6838.73 14329.02,6838.73 cw(c14329.02,6846.23) 14329.02,6853.73 14344.86,6853.73 ccw(c14344.86,6861.23) 14344.86,6868.73 14329.02,6868.73 cw(c14329.02,6876.23) 14329.02,6883.73 14344.86,6883.73 ccw(c14344.86,6891.23) 14344.86,6898.73 14329.02,6898.73 cw(c14329.02,6906.23) 14329.02,6913.73 14344.86,6913.73 ccw(c14344.86,6921.23) 14352.36,6921.23 14352.36,6963.7 RN15.8@14352.83,6964.17
7125_R5_FPGA: RN15.1 U8.AA8 | length 604.1
  Top Layer w4.7: v3(14352.36,7026) 14352.83,7025.53 RN15.1@14352.83,6997.83
  Top Layer w10: v2(14449.89,7522.32) U8.AA8@14469.56,7542
  L6_SIG2 w5: v3(14352.36,7026) 14352.36,7039 14463.36,7150 14463.36,7508.85 v2(14449.89,7522.32)
7125_R6: RN20.5 U4.47 | length 1107.8
  Top Layer w4.7: U4.47@14185.22,6418.58 14207.94,6418.58 14264.92,6475.56 ccw(c14261.38,6479.1) 14264.92,6482.63 14245.53,6502.02 cw(c14249.06,6505.56) 14252.6,6509.09 14271.99,6489.7 ccw(c14275.53,6493.24) 14279.06,6496.77 14259.67,6516.16 cw(c14263.21,6519.7) 14266.74,6523.24 14286.13,6503.85 ccw(c14289.67,6507.38) 14293.2,6510.92 14273.81,6530.31 cw(c14277.35,6533.84) 14280.88,6537.38 14300.27,6517.99 ccw(c14303.81,6521.52) 14307.35,6517.99 14311.36,6522 14311.36,6536.36 cw(c14316.36,6536.36) 14316.36,6541.36 14337.22,6541.36 ccw(c14337.22,6546.36) 14337.22,6551.36 14316.36,6551.36 cw(c14316.36,6556.36) 14316.36,6561.36 14337.22,6561.36 ccw(c14337.22,6566.36) 14337.22,6571.36 14316.36,6571.36 cw(c14316.36,6576.36) 14316.36,6581.36 14337.22,6581.36 ccw(c14337.22,6586.36) 14337.22,6591.36 14316.36,6591.36 cw(c14316.36,6596.36) 14316.36,6601.36 14337.22,6601.36 ccw(c14337.22,6606.36) 14337.22,6611.36 14316.36,6611.36 cw(c14316.36,6616.36) 14316.36,6621.36 14337.22,6621.36 ccw(c14337.22,6626.36) 14337.22,6631.36 14316.36,6631.36 cw(c14316.36,6636.36) 14311.36,6636.36 14311.36,6827.49 ccw(c14306.68,6827.49) 14306.68,6832.16 cw(c14306.68,6836.84) 14302.01,6836.84 14302.01,6837.49 cw(c14306.68,6837.49) 14306.68,6842.16 ccw(c14306.68,6846.84) 14311.36,6846.84 14311.36,6847.49 ccw(c14306.68,6847.49) 14306.68,6852.16 cw(c14306.68,6856.84) 14302.01,6856.84 14302.01,6857.49 cw(c14306.68,6857.49) 14306.68,6862.16 ccw(c14306.68,6866.84) 14311.36,6866.84 14311.36,6867.49 ccw(c14306.68,6867.49) 14306.68,6872.16 cw(c14306.68,6876.84) 14302.01,6876.84 14302.01,6877.49 cw(c14306.68,6877.49) 14306.68,6882.16 ccw(c14306.68,6886.84) 14311.36,6886.84 14311.36,6963.64 RN20.5@14311.89,6964.17
7125_R6_FPGA: RN20.4 U8.AB8 | length 570.1
  Top Layer w4.7: RN20.4@14311.89,6997.83 14311.89,7023.53 v3(14319.36,7031)
  Top Layer w10: v2(14449.89,7482.92) U8.AB8@14469.56,7502.6
  L6_SIG2 w5: v3(14319.36,7031) 14449.89,7161.53 v2(14449.89,7482.92)
7125_R7: RN20.6 U4.48 | length 841.5
  Top Layer w4.7: U4.48@14185.22,6438.27 14231.54,6484.59 14231.54,6538.3 cw(c14236.54,6538.3) 14236.54,6543.3 14254.31,6543.3 ccw(c14254.31,6548.3) 14254.31,6553.3 14236.54,6553.3 cw(c14236.54,6558.3) 14236.54,6563.3 14254.31,6563.3 ccw(c14254.31,6568.3) 14254.31,6573.3 14236.54,6573.3 cw(c14236.54,6578.3) 14231.54,6578.3 14231.54,6595.59 14242.77,6606.82 cw(c14246.31,6603.28) 14249.84,6606.82 14276.95,6579.71 ccw(c14280.49,6583.25) 14284.02,6586.78 14256.91,6613.89 cw(c14260.45,6617.43) 14263.99,6620.96 14291.09,6593.85 ccw(c14294.63,6597.39) 14298.16,6600.93 14271.06,6628.03 cw(c14274.59,6631.57) 14271.06,6635.1 14293.71,6657.75 14293.71,6962.66 RN20.6@14292.25,6964.12
7125_R7_FPGA: RN20.3 U8.T7 | length 820.1
  Top Layer w4.7: RN20.3@14292.2,6997.83 14292.2,7025.84 v3(14294.36,7028)
  Top Layer w10: v2(14410.52,7719.16) U8.T7@14430.19,7738.84
  L6_SIG2 w5: v3(14294.36,7028) 14294.36,7037 14437.04,7179.68 14437.04,7692.64 v2(14410.52,7719.16)
7125_SYC: R82.2 RN18.8 U4.12 | length 1029.5
  Top Layer w4.7: v3(13907.36,6476) 13907.36,6470 13914.36,6463 13940.74,6463 13942.23,6461.5 13942.23,6470.24 13905.1,6507.38 ccw(c13895.1,6507.38) 13895.1,6517.38 13869.97,6517.38 cw(c13869.97,6527.38) 13869.97,6537.38 13895.1,6537.38 ccw(c13895.1,6547.38) 13895.1,6557.38 13869.97,6557.38 cw(c13869.97,6567.38) 13869.97,6577.38 13895.1,6577.38 ccw(c13895.1,6587.38) 13895.1,6597.38 13869.97,6597.38 cw(c13869.97,6607.38) 13869.97,6617.38 13895.1,6617.38 ccw(c13895.1,6627.38) 13895.1,6637.38 13869.97,6637.38 cw(c13869.97,6647.38) 13869.97,6657.38 13895.1,6657.38 ccw(c13895.1,6667.38) 13895.1,6677.38 13869.97,6677.38 cw(c13869.97,6687.38) 13869.97,6697.38 13895.1,6697.38 ccw(c13895.1,6707.38) 13905.1,6707.38 13905.1,6785.75 14052.36,6932.9 14052.36,6963.7 RN18.8@14052.83,6964.17
  Bottom Layer w4.7: v3(13907.36,6476) 13907.36,6514.96 R82.2@13908.36,6515.96
7125_SYC_FPGA: RN18.1 U8.V5 | length 786.4
  Top Layer w4.7: v3(14052.36,7031) 14052.83,7030.53 RN18.1@14052.83,6997.83
  Top Layer w10: v2(14331.79,7640.42) U8.V5@14351.46,7660.1
  L6_SIG2 w5: v3(14052.36,7031) 14052.36,7065 14305.36,7318 14305.36,7613.99 v2(14331.79,7640.42)
7125_VGA_HSYC: Q3.2 R92.1 RN24.7 | length 1772.2
  Top Layer w4.7: Q3.2@13699.65,5935.41 13720.01,5955.77 R92.1@13720.01,5996.04 13720.01,6034.35 v3(13719.36,6035) ; v3(14572.36,6937) 14572.36,6964.01 RN24.7@14572.52,6964.17
  L6_SIG2 w5: v3(13719.36,6035) 13767.36,6083 14418.36,6083 14572.36,6237 v3(14572.36,6937)
7125_VGA_HSYC_FPGA: RN24.2 U8.T8 | length 811.4
  Top Layer w4.7: RN24.2@14572.52,6997.83 14572.78,6998.09 v4(14572.78,7021)
  Top Layer w10: v2(14449.89,7719.16) U8.T8@14469.56,7738.84
  L3_SIG1 w5: v2(14449.89,7719.16) 14436.36,7705.63 14436.36,7165 14572.78,7028.58 v4(14572.78,7021)
7125_VGA_SCL: Q2.2 R89.1 RN24.6 | length 2148.6
  Top Layer w4.7: Q2.2@13408.96,5934.72 13430.01,5955.77 R89.1@13430.01,5991.04 v3(13430.01,6036) ; RN24.6@14592.2,6964.17 14592.2,6939.16 v3(14592.36,6939)
  L3_SIG1 w5: v3(13430.01,6036) 13474.01,5992 14397.36,5992 14592.36,6187 v3(14592.36,6939)
7125_VGA_SCL_FPGA: RN24.3 U8.U8 | length 768.9
  Top Layer w4.7: RN24.3@14592.2,6997.83 14592.2,7034.84 v4(14592.36,7035)
  Top Layer w10: v2(14449.89,7679.79) U8.U8@14469.56,7699.47
  L3_SIG1 w5: v2(14449.89,7679.79) 14463.36,7666.32 14463.36,7164 v4(14592.36,7035)
7125_VGA_SDA: Q1.2 R88.1 RN24.5 | length 1999.9
  Top Layer w4.7: Q1.2@13554.65,5935.41 13575.01,5955.77 R88.1@13575.01,5996.04 v3(13575.01,6035) ; v3(14611.36,6925) 14611.89,6925.53 RN24.5@14611.89,6964.17
  L6_SIG2 w5: v3(13575.01,6035) 13594.01,6016 14439.36,6016 14611.36,6188 v3(14611.36,6925)
7125_VGA_SDA_FPGA: RN24.4 U8.R9 | length 850.8
  Top Layer w4.7: v4(14610.36,7021) 14611.89,7019.47 RN24.4@14611.89,6997.83
  Top Layer w10: v2(14489.26,7758.52) U8.R9@14508.93,7778.2
  L3_SIG1 w5: v2(14489.26,7758.52) 14475.36,7744.62 14475.36,7179 14610.36,7044 v4(14610.36,7021)
7125_VGA_VSYC: Q4.2 R93.1 RN24.8 | length 1616.2
  Top Layer w4.7: Q4.2@13844.65,5935.41 13865.01,5955.77 R93.1@13865.01,5996.04 13865.01,6034.65 v3(13865.36,6035) ; v3(14551.36,6926) 14552.83,6927.47 RN24.8@14552.83,6964.17
  L3_SIG1 w5: v3(13865.36,6035) 14367.36,6035 14551.36,6219 v3(14551.36,6926)
7125_VGA_VSYC_FPGA: RN24.1 U8.R8 | length 852.3
  Top Layer w4.7: v4(14537.36,7023) 14552.83,7007.53 RN24.1@14552.83,6997.83
  Top Layer w10: v2(14449.89,7758.52) U8.R8@14469.56,7778.2
  L3_SIG1 w5: v2(14449.89,7758.52) 14424.38,7733.02 14424.38,7154.97 14537.36,7042 v4(14537.36,7023)
7125_VREF: C111.2 R87.1 U4.36 U13.1 | length 227.1
  Top Layer w10: U4.36@14159.12,6195.55 14168.01,6186.66 14280.64,6186.66 U13.1@14283.2,6189.22
  Top Layer w20: U13.1@14287.73,6192.4 14289.32,6193.98 R87.1@14289.32,6290
7393_PVDD: C331.1 C332.2 C341.2 C342.2 L38.2 U111.23 | length 308.3
  Top Layer w10: U111.23@17181.77,7800.06 v4(17209.19,7800.06) 17234.76,7800.06 C341.2@17237.36,7797.46 17257.23,7817.34 C342.2@17285.07,7817.34
  Bottom Layer w20: v4(17209.19,7800.06) 17229.22,7800.06 C332.2@17285.12,7744.15 C331.1@17285.12,7704.15 17285.12,7653.06 L38.2@17289.03,7649.15
7393_PWR: C329.2 L37.1 L39.2 L41.1
  other v1: 16925.58,8142.41 17260.63,8142.47 16967.53,8142.97 17304.96,8143.46 16966.54,8179.16 16926.19,8179.83 17260.63,8179.83 17304.47,8179.83
7393_PWR1V8: C338.2 L38.1 L40.1 L42.2 | length 126.1
  Bottom Layer w50: L42.2@17231.47,8357 17356.9,8357 C338.2@17357.36,8356.54
  other v1: 17456.36,8342 17507.36,8343 17456.36,8379 17507.36,8379
7393_VAA: C319.1 C322.1 C330.2 D31.2 D32.2 D33.2 L37.2 U111.25 U112.2 | length 1320.7
  Top Layer w10: U111.25@17181.77,7839.43 v3(17241.36,7839.43)
  Top Layer w20: D32.2@17469.96,8024.36 v3(17469.96,8078) ; D33.2@17469.96,8241.36 v3(17469.96,8298) ; D31.2@17544.76,7737.64 17544.76,7693.6 v3(17545.36,7693)
  Bottom Layer w10: U112.2@17293.82,7921 17297.36,7917.46 C330.2@17297.36,7842.46
  Bottom Layer w15: L37.2@17406.36,7929.44 L37.2@17413.91,7937 ; v3(17469.96,8298) v3(17469.96,8078) 17469.96,7947.6 17460.36,7938 17414.91,7938 L37.2@17413.91,7937 ; v3(17545.36,7693) 17545.36,7894 17502.36,7937 L37.2@17413.91,7937
  Bottom Layer w20: v3(17241.36,7839.43) 17244,7842.07 C319.1@17338.04,7842.07 17406.19,7842.07 C322.1@17407.36,7843.24 17407.36,7928.44 L37.2@17406.36,7929.44
7393_VDD: C333.1 C334.2 C339.1 C340.2 L40.2 U111.6 U111.35 | length 314.9
  Top Layer w10: v3(16908.16,7839.23) 16908.65,7839.72 U111.6@16947.21,7839.72 ; U111.35@17073.5,7967.38 v3(17073.5,8017)
  Bottom Layer w10: v3(16908.16,7839.23) v3@16908.16,7839.48
  Bottom Layer w20: C339.1@16866.91,7871.64 16866.91,7773.42 L40.2@16868.38,7771.95 ; C340.2@16870.24,7836.88 16872.58,7839.23 v3(16908.16,7839.23) ; C334.2@17051.58,8052.69 17091.96,8052.69 C333.1@17092.97,8053.71 17092.97,8036.48 v3(17073.5,8017)
7393_VDDIO: C335.1 C336.2 C346.1 C348.1 C350.1 D34.3 L41.2 R171.2 U111.1 U115.23 U115.24 U116.23 U116.24 U117.23 U117.24 | length 1998.8
  Top Layer w10: v3(16867.36,7626) 16873.14,7631.79 R171.2@16910,7631.79
  Top Layer w15: U117.23@16456.36,7466.15 16531.07,7466.15 C348.1@16540.36,7475.44 ; U117.24@16456.36,7491.74 16524.06,7491.74 C348.1@16540.36,7475.44 ; U116.23@16456.36,7796.15 C350.1@16540.07,7796.15 ; U116.24@16456.36,7821.74 16519.06,7821.74 C350.1@16542.36,7798.44 C350.1@16540.07,7796.15 ; U115.23@16456.36,8126.15 16520.07,8126.15 C346.1@16542.36,8148.44 ; U115.24@16456.36,8151.74 16539.06,8151.74 C346.1@16542.36,8148.44 ; v3(16615.36,7475) 16614.92,7475.44 C348.1@16540.36,7475.44 ; v3(16681.36,7854) 16623.51,7796.15 C350.1@16540.07,7796.15 ; v3(16697.36,8148.44) C346.1@16542.36,8148.44 ; v3(16878.36,7937.85) U111.1@16945.55,7937.85
  L6_SIG2 w10: v4@16724.25,7487.29 16724.69,7486.85 v3(17338.08,7486.85) ; v4@16725.67,7577.79 16819.15,7577.79 v3(16867.36,7626)
  Bottom Layer w10: D34.3@17298.73,7486.41 17337.64,7486.41 v3(17338.08,7486.85)
  Bottom Layer w15: v3(16878.36,7937.85) 16879.49,7938.98 C336.2@16879.49,7978.05 C335.1@16879.49,8018.05 16880.8,8019.36 L41.2@16880.8,8069
  other v4: 16726.01,7486.69 16724.95,7579.27
$1N7986: R6.2 U8.AB20 | length 79.8
  Top Layer w10: U8.AB20@14942,7502.6 v2(14961.68,7482.92)
  Bottom Layer w4.7: v2(14961.68,7482.92) 14978.48,7482.92 R6.2@15003.36,7458.04
$1N7989: R7.2 U8.AA20 | length 108.9
  Top Layer w10: U8.AA20@14942,7542 v2(14961.68,7522.32)
  Bottom Layer w4.7: v2(14961.68,7522.32) 14958.68,7522.32 14944.36,7508 14944.36,7477.04 R7.2@14963.36,7458.04
$1N8006: R11.2 U8.Y21 | length 148.6
  Top Layer w10: U8.Y21@14981.36,7581.35 v2(15001.04,7561.68)
  Bottom Layer w4.7: v2(15001.04,7561.68) 15026.31,7536.41 15026.31,7474.09 R11.2@15042.36,7458.04
$1N8153: R12.2 U8.T5 | length 2227.5
  Top Layer w4.7: R12.2@15844.4,7197 15866.36,7197 v3(15892.36,7171)
  Top Layer w10: v2(14331.79,7719.16) U8.T5@14351.46,7738.84
  L3_SIG1 w5: v2(14331.79,7719.16) 14352.36,7739.73 14352.36,7793 14370.36,7811 14590.36,7811 14604.36,7797 14604.36,7377 14810.36,7171 v3(15892.36,7171)
$1N8351: R13.2 U8.U13 | length 1017.7
  Top Layer w4.7: v3(15258.36,7199) 15262.32,7199 R13.2@15295.32,7232
  Top Layer w10: U8.U13@14666.41,7699.47 v2(14686.09,7679.79)
  L3_SIG1 w5: v2(14686.09,7679.79) 14707.36,7658.52 14707.36,7433 14824.36,7316 15202.36,7316 15258.36,7260 v3(15258.36,7199)
$1N8353: R14.2 U8.U14 | length 1509
  Top Layer w4.7: v3(15587.36,7341) 15587.36,7381 15633.36,7427 15831.36,7427 15844.36,7414 R14.2@15844.4,7380
  Top Layer w10: U8.U14@14705.78,7699.47 v2(14725.46,7679.79)
  L3_SIG1 w5: v2(14725.46,7679.79) 14751.36,7653.89 14751.36,7443 14824.36,7370 15558.36,7370 v3(15587.36,7341)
